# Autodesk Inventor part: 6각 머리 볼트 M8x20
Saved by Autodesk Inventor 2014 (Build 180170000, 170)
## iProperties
Created: 2025-12
Part Number: 6각 머리 볼트 M8x20
Material: 일반
Document SubType Name: Modeling
Designer: dg
Density: 1 g/cm^3
Appearance: 기본값
Author: dg
Author: jhkim
Description: 6각 머리 볼트 및 6각 머리 나사
Creation Date: 2025-11-19
Sending System: Autodesk Inventor 2026
Preprocessor: ST-DEVELOPER v20.1
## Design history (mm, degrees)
node "6각 머리 볼트 M8x201"
body "Solid1"
node "기준1"
